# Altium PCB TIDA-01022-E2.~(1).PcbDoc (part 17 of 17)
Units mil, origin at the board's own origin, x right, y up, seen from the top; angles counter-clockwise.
Board outline 6929.13 x 11614.17 mil, 12 copper layers (L1_Top Layer, L2_GND, L3_GND, L4_Signal Layer 1, L5_GND, L6_PWR, L7_GND/PWR, L8_PWR, L9_GND/PWR, L10_Signal Layer 2, L11_GND, L12_Bottom Layer), stack 64.6 mil thick; 1711 components, 1001 nets, 5985 pads, 3200 vias.
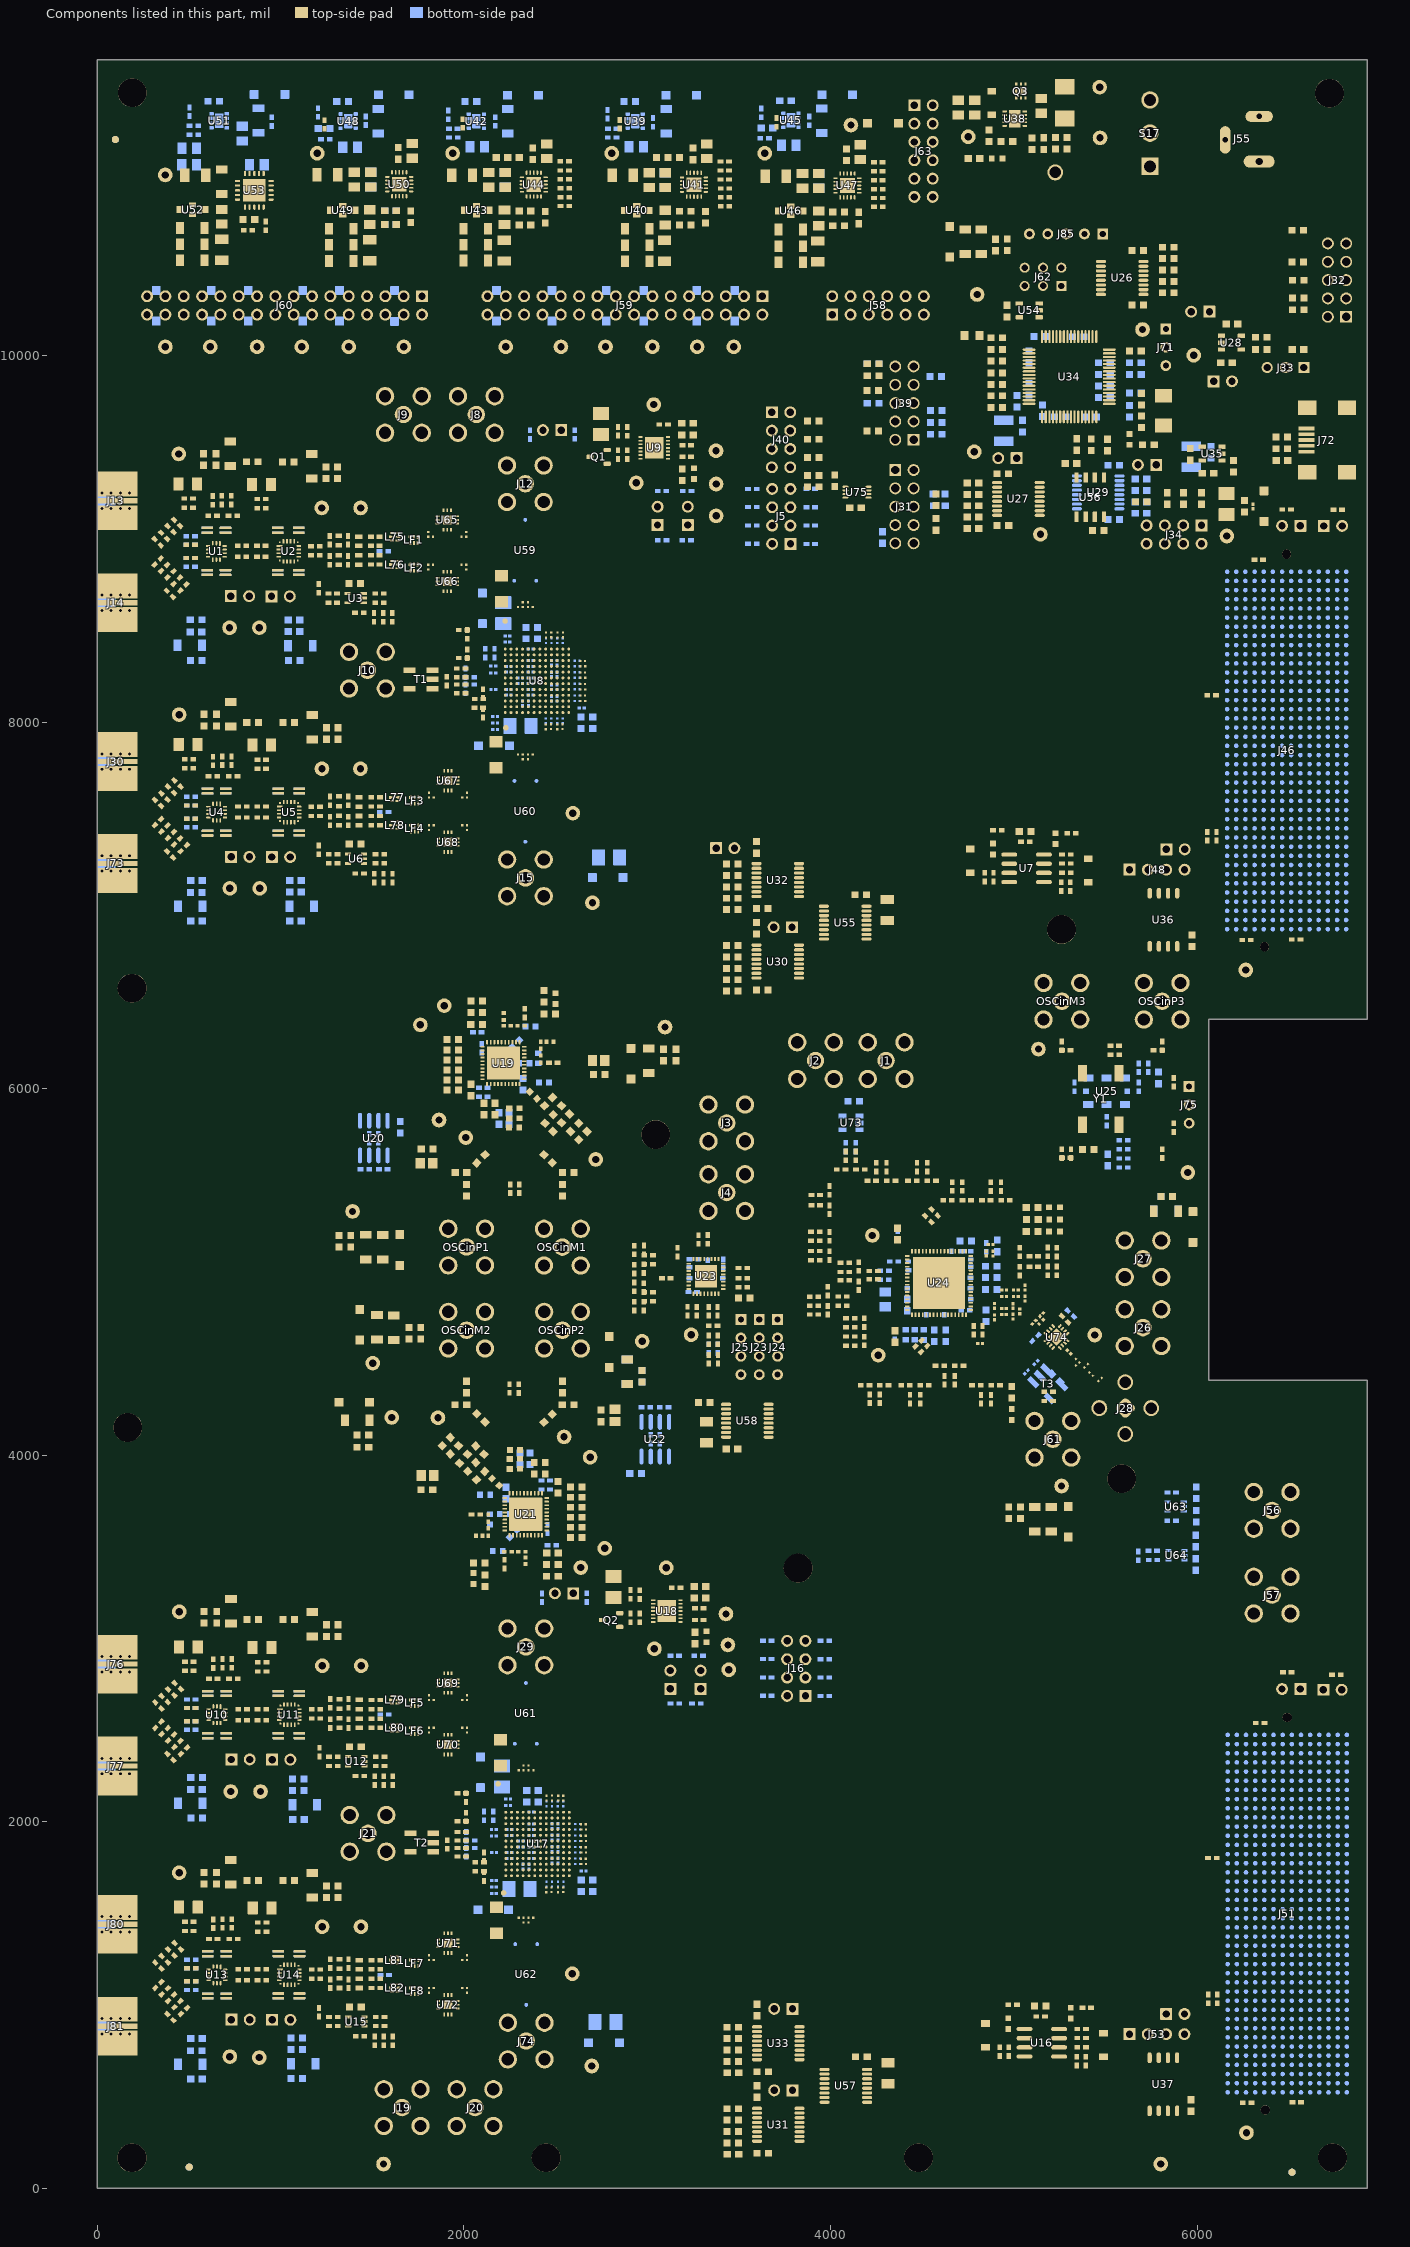
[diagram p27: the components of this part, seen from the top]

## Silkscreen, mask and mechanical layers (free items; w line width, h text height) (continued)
M12 Stackup:
  drawing of 711 lines, arcs and shapes, not listed
  text "STACKUP:-" at 7625.42,4857.9 h60
  text "Layer" at 7653.5,4547.5 h60
  text "Name" at 8063.41,4547.5 h60
  text "Material" at 9233.08,4547.5 h60
  text "Thickness" at 10092.85,4547.5 h60
  text "Constant" at 10742.68,4547.5 h60
  text "Board Layer Stack" at 11312.54,4547.5 h60
  text "1" at 7653.5,4427.5 h60
  text "Top Overlay" at 8063.41,4427.5 h60
  text "2" at 7653.5,4307.5 h60
  text "Top Solder" at 8063.41,4307.5 h60
  text "Solder Resist" at 9233.08,4307.5 h60
  text "0.40mil" at 10092.85,4307.5 h60
  text "3.5" at 10742.68,4307.5 h60
  text "3" at 7653.5,4187.5 h60
  text "L1_Top Layer" at 8063.41,4187.5 h60
  text "Copper" at 9233.08,4187.5 h60
  text "1.40mil" at 10092.85,4187.5 h60
  text "4" at 7653.5,4067.5 h60
  text "Dielectric1" at 8063.41,4067.5 h60
  text "R-5670k" at 9233.08,4067.5 h60
  text "5.60mil" at 10092.85,4067.5 h60
  text "4.2" at 10742.68,4067.5 h60
  text "5" at 7653.5,3947.5 h60
  text "L2_GND" at 8063.41,3947.5 h60
  text "Copper" at 9233.08,3947.5 h60
  text "0.60mil" at 10092.85,3947.5 h60
  text "6" at 7653.5,3827.5 h60
  text "Dielectric 2" at 8063.41,3827.5 h60
  text "R-5775K" at 9233.08,3827.5 h60
  text "5.00mil" at 10092.85,3827.5 h60
  text "4.2" at 10742.68,3827.5 h60
  text "7" at 7653.5,3707.5 h60
  text "L3_GND" at 8063.41,3707.5 h60
  text "Copper" at 9233.08,3707.5 h60
  text "0.60mil" at 10092.85,3707.5 h60
  text "8" at 7653.5,3587.5 h60
  text "Dielectric 3" at 8063.41,3587.5 h60
  text "R-5670k" at 9233.08,3587.5 h60
  text "7.50mil" at 10092.85,3587.5 h60
  text "4.2" at 10742.68,3587.5 h60
  text "9" at 7653.5,3467.5 h60
  text "L4_Signal Layer 1" at 8063.41,3467.5 h60
  text "Copper" at 9233.08,3467.5 h60
  text "0.60mil" at 10092.85,3467.5 h60
  text "10" at 7653.5,3347.5 h60
  text "Dielectric 4" at 8063.41,3347.5 h60
  text "R-5775K" at 9233.08,3347.5 h60
  text "4.00mil" at 10092.85,3347.5 h60
  text "4.2" at 10742.68,3347.5 h60
  text "11" at 7653.5,3227.5 h60
  text "L5_GND" at 8063.41,3227.5 h60
  text "Copper" at 9233.08,3227.5 h60
  text "0.60mil" at 10092.85,3227.5 h60
  text "12" at 7653.5,3107.5 h60
  text "Dielectric 5" at 8063.41,3107.5 h60
  text "R-5670k" at 9233.08,3107.5 h60
  text "4.30mil" at 10092.85,3107.5 h60
  text "4.2" at 10742.68,3107.5 h60
  text "13" at 7653.5,2987.5 h60
  text "L6_PWR" at 8063.41,2987.5 h60
  text "Copper" at 9233.08,2987.5 h60
  text "0.60mil" at 10092.85,2987.5 h60
  text "14" at 7653.5,2867.5 h60
  text "Dielectric 6" at 8063.41,2867.5 h60
  text "R-5775K" at 9233.08,2867.5 h60
  text "3.00mil" at 10092.85,2867.5 h60
  text "4.2" at 10742.68,2867.5 h60
  text "15" at 7653.5,2747.5 h60
  text "L7_GND/PWR" at 8063.41,2747.5 h60
  text "Copper" at 9233.08,2747.5 h60
  text "0.60mil" at 10092.85,2747.5 h60
  text "16" at 7653.5,2627.5 h60
  text "Dielectric 7" at 8063.41,2627.5 h60
  text "R-5670k" at 9233.08,2627.5 h60
  text "4.30mil" at 10092.85,2627.5 h60
  text "4.2" at 10742.68,2627.5 h60
  text "17" at 7653.5,2507.5 h60
  text "L8_PWR" at 8063.41,2507.5 h60
  text "Copper" at 9233.08,2507.5 h60
  text "0.60mil" at 10092.85,2507.5 h60
  text "18" at 7653.5,2387.5 h60
  text "Dielectric 8" at 8063.41,2387.5 h60
  text "R-5775K" at 9233.08,2387.5 h60
  text "4.00mil" at 10092.85,2387.5 h60
  text "4.2" at 10742.68,2387.5 h60
  text "19" at 7653.5,2267.5 h60
  text "L9_GND/PWR" at 8063.41,2267.5 h60
  text "Copper" at 9233.08,2267.5 h60
  text "0.60mil" at 10092.85,2267.5 h60
  text "20" at 7653.5,2147.5 h60
  text "Dielectric 9" at 8063.41,2147.5 h60
  text "R-5670k" at 9233.08,2147.5 h60
  text "7.50mil" at 10092.85,2147.5 h60
  text "4.2" at 10742.68,2147.5 h60
  text "21" at 7653.5,2027.5 h60
  text "L10_Signal Layer 2" at 8063.41,2027.5 h60
  text "Copper" at 9233.08,2027.5 h60
  text "0.60mil" at 10092.85,2027.5 h60
  text "22" at 7653.5,1907.5 h60
  text "Dielectric 10" at 8063.41,1907.5 h60
  text "R-5775K" at 9233.08,1907.5 h60
  text "5.00mil" at 10092.85,1907.5 h60
  text "4.2" at 10742.68,1907.5 h60
  text "23" at 7653.5,1787.5 h60
  text "L11_GND" at 8063.41,1787.5 h60
  text "Copper" at 9233.08,1787.5 h60
  text "0.60mil" at 10092.85,1787.5 h60
  text "24" at 7653.5,1667.5 h60
  text "Dielectric 11" at 8063.41,1667.5 h60
  text "R-5670k" at 9233.08,1667.5 h60
  text "5.60mil" at 10092.85,1667.5 h60
  text "4.2" at 10742.68,1667.5 h60
  text "25" at 7653.5,1547.5 h60
  text "L12_Bottom Layer" at 8063.41,1547.5 h60
  text "Copper" at 9233.08,1547.5 h60
  text "1.40mil" at 10092.85,1547.5 h60
  text "26" at 7653.5,1427.5 h60
  text "Bottom Solder" at 8063.41,1427.5 h60
  text "Solder Resist" at 9233.08,1427.5 h60
  text "0.40mil" at 10092.85,1427.5 h60
  text "3.5" at 10742.68,1427.5 h60
  text "27" at 7653.5,1307.5 h60
  text "Bottom Overlay" at 8063.41,1307.5 h60
M13 Component Bodies Top:
  text ".Layer_Name" at -2293.76,-2323.68 h60
M14 Component Bodies Bottom:
  text ".Layer_Name" at -2293.76,-2323.68 h60
M15 Courtyards Top:
  text ".Layer_Name" at -2293.76,-2323.68 h60
M16 Courtyards Bottom:
  text ".Layer_Name" at -2293.76,-2323.68 h60
Drill Drawing:
  text ".legend" at 8215.24,7564.81 h60
  text "Drill Table" at 8271.47,7429.81 h60
  text "FOR 8MIL DRILL +0/-8MIL" at 8250.24,7188.81 h60
  text "FOR 12MIL DRILL +0/-12MIL" at 8250.24,7099.81 h60
  text "FOR 16MIL DRILL +0/-16MIL" at 8244.24,7004.81 h60
  text "FOR PTH DRILL +/-3MIL" at 8237.46,6900.81 h60
  text "FOR NPTH DRILL +/-2MIL" at 8237.46,6820.81 h60
  text "NOTE:" at 8213.46,6659.81 h60
  text "Fill all on pad vias and flat the surface" at 8485.68,6531.9 h60
  text "DRILL DRAWING" at -2293.76,-2323.68 h60

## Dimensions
0,11614.17 to 0,0 on M2 Board Dimensions
6929.13,6377.95 to 6929.13,11614.17 on M2 Board Dimensions
6062.99,6377.95 to 6062.99,4409.45 on M2 Board Dimensions
6062.99,4409.45 to 6929.13,4409.45 on M2 Board Dimensions
6929.13,4409.45 to 6929.13,0 on M2 Board Dimensions
0,0 to 6929.13,0 on M2 Board Dimensions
